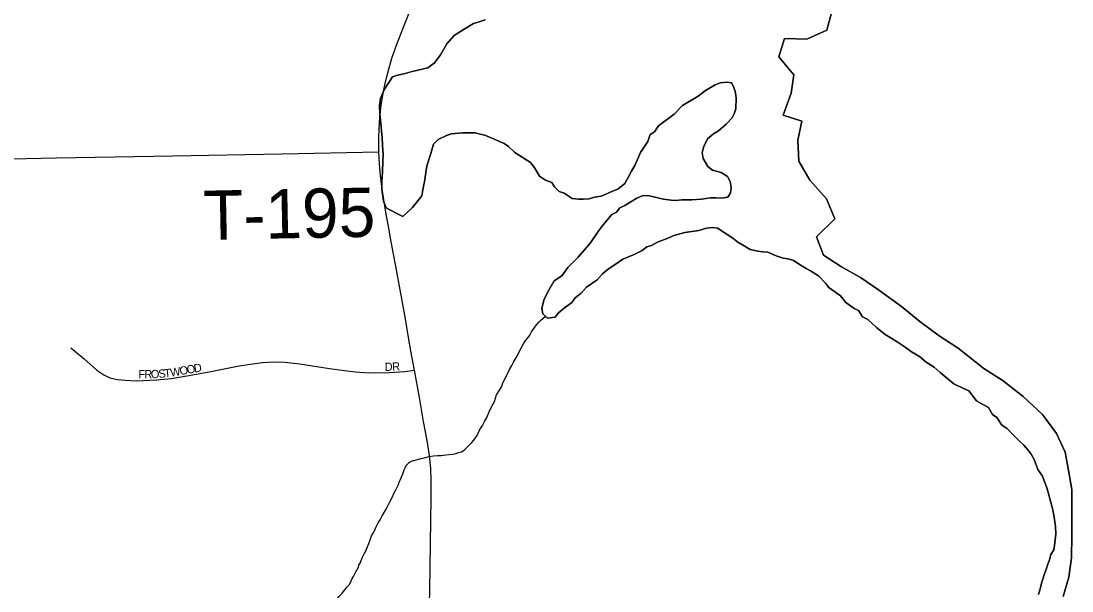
# Model space of a CAD drawing. Extents: x -10.1 to 68, y -9.5 to 29.2.
# Drawn here: x 4.36 to 5.573, y 17.444 to 18.102 of the extents above; entities that cross this region are included whole.
import ezdxf

# ---------------------------------------------------------------- set-up
doc = ezdxf.new("R2010")
doc.units = 0
for name, color, linetype in [('GM_X_Major_Lake', 7, 'Continuous'), ('GM_X_Major_River', 7, 'Continuous'), ('GM_X_Minor_River', 7, 'Continuous'), ('GM_X_Township_Road', 7, 'Continuous'), ('GM_X_Township_Road_Text', 7, 'Continuous'), ('GM_X_Township_Subdivision', 7, 'Continuous'), ('GM_X_Township_Subdivision_Text', 7, 'Continuous'), ('SH_Data', 7, 'Continuous')]:
    doc.layers.add(name, color=color, linetype=linetype)

msp = doc.modelspace()

# ---------------------------------------------------------------- linework, layer by layer
at = {"layer": 'GM_X_Major_Lake'}
for points in [[(4.896, 18.1037), (4.8877, 18.1009), (4.8824, 18.0993), (4.8715, 18.0927), (4.8602, 18.0854), (4.8516, 18.0758), (4.8442, 18.0631), (4.8375, 18.0539), (4.8296, 18.0481), (4.8115, 18.0441), (4.8035, 18.0417), (4.7937, 18.0393), (4.7888, 18.0377), (4.7799, 18.0235), (4.7751, 18.0132), (4.774, 18.0048), (4.7745, 17.995), (4.7754, 17.9843), (4.7763, 17.9752), (4.7771, 17.9676), (4.7776, 17.9589), (4.7781, 17.9479), (4.7778, 17.9403), (4.7776, 17.9277), (4.7766, 17.9171), (4.7767, 17.9087), (4.7784, 17.8943), (4.7815, 17.8867), (4.7933, 17.8804), (4.8009, 17.8767), (4.8122, 17.8871), (4.8226, 17.9006), (4.824, 17.9074), (4.8262, 17.9189), (4.8276, 17.9303), (4.829, 17.9364), (4.833, 17.9494), (4.8363, 17.96), (4.8415, 17.9654), (4.8513, 17.9701), (4.857, 17.9721), (4.8699, 17.973), (4.8843, 17.9732), (4.89, 17.9717), (4.8953, 17.9703), (4.9063, 17.9659), (4.9178, 17.9607), (4.9227, 17.9573), (4.93, 17.9506), (4.9483, 17.939), (4.9533, 17.9323), (4.9587, 17.9232), (4.9656, 17.9187), (4.9728, 17.9158), (4.9759, 17.9109), (4.9813, 17.9056), (4.987, 17.9034), (4.9962, 17.8975), (5.0038, 17.8964), (5.0091, 17.8965)], [(5.286, 17.832), (5.2782, 17.8532), (5.2991, 17.874), (5.2898, 17.897), (5.2706, 17.9184), (5.2578, 17.9403), (5.2564, 17.9646), (5.2611, 17.9867), (5.2398, 17.9937), (5.2489, 18.0189), (5.2521, 18.0402), (5.2348, 18.0609), (5.241, 18.0822), (5.2671, 18.0814), (5.2901, 18.0916), (5.2959, 18.1133)], [(5.0091, 17.8965), (5.0159, 17.897), (5.0219, 17.8989), (5.0295, 17.9002), (5.0344, 17.9018), (5.0427, 17.9057), (5.0491, 17.908), (5.057, 17.9146), (5.0614, 17.9222), (5.0647, 17.9291), (5.0688, 17.9364), (5.0751, 17.9505), (5.0837, 17.9632), (5.0862, 17.9712), (5.0911, 17.9743), (5.096, 17.9812), (5.114, 17.9947), (5.1237, 18.0047), (5.1331, 18.0106), (5.1414, 18.0156), (5.15, 18.0222), (5.1613, 18.0284), (5.167, 18.0307), (5.1749, 18.0316), (5.1802, 18.0309), (5.1829, 18.026), (5.1845, 18.0192), (5.1854, 18.0131), (5.1851, 18.001), (5.1833, 17.9952), (5.1807, 17.9903), (5.174, 17.9833), (5.165, 17.9756), (5.1593, 17.9721), (5.1522, 17.9663), (5.1481, 17.9575), (5.1463, 17.9503), (5.1472, 17.9435), (5.1529, 17.9344), (5.1583, 17.9299), (5.1682, 17.9274), (5.1754, 17.9229), (5.1785, 17.9169), (5.1798, 17.9101), (5.1787, 17.904), (5.1757, 17.899), (5.1678, 17.8977), (5.1617, 17.8981), (5.1557, 17.898), (5.1507, 17.8972), (5.1454, 17.8967), (5.1341, 17.8958), (5.1227, 17.8957), (5.1155, 17.8952), (5.1106, 17.8955), (5.1015, 17.8965), (5.0966, 17.8976), (5.0855, 17.9005), (5.078, 17.9008), (5.0708, 17.8977), (5.0569, 17.8891), (5.0512, 17.8864), (5.0475, 17.8814), (5.0418, 17.879), (5.0321, 17.8671), (5.0262, 17.8591), (5.0172, 17.846), (5.0127, 17.8407), (5.003, 17.8295), (4.9914, 17.8176), (4.9843, 17.808), (4.9753, 17.8022), (4.9683, 17.7896), (4.9635, 17.78), (4.9613, 17.7705), (4.9625, 17.7644), (4.9679, 17.7592), (4.9766, 17.7604), (4.9803, 17.7654), (4.987, 17.7708), (4.9957, 17.7774), (4.9998, 17.7827), (5.0065, 17.7881), (5.0129, 17.7951), (5.0249, 17.8036), (5.0313, 17.8105), (5.038, 17.8163), (5.0482, 17.8229), (5.0546, 17.8275), (5.0678, 17.8326), (5.0768, 17.8373), (5.0824, 17.8416), (5.0877, 17.8431), (5.0945, 17.847), (5.1077, 17.8518), (5.1134, 17.8545), (5.1262, 17.8581), (5.1368, 17.8597), (5.1425, 17.8606), (5.1511, 17.8633), (5.1583, 17.8638)], [(5.1583, 17.8638), (5.164, 17.8631), (5.1717, 17.8583), (5.1816, 17.8516), (5.1873, 17.8471), (5.1946, 17.8426), (5.2014, 17.8385), (5.2105, 17.8367), (5.2162, 17.8357), (5.2219, 17.8354), (5.2314, 17.8313), (5.2398, 17.8284), (5.2455, 17.8277), (5.2516, 17.8259), (5.2604, 17.8199), (5.2661, 17.8165), (5.2711, 17.8139), (5.2806, 17.808)], [(5.5626, 17.438), (5.5692, 17.4601), (5.5723, 17.4826), (5.5728, 17.5081), (5.5728, 17.5366), (5.5726, 17.5613), (5.5689, 17.5833), (5.5649, 17.6045), (5.5551, 17.626), (5.539, 17.6482), (5.5164, 17.6689), (5.4934, 17.6868), (5.4713, 17.701), (5.4414, 17.7245), (5.4197, 17.7387), (5.3975, 17.7555), (5.3761, 17.7727), (5.3497, 17.7918), (5.3287, 17.8063), (5.307, 17.8186), (5.286, 17.832)], [(5.2806, 17.808), (5.2883, 17.7997), (5.2925, 17.7945), (5.3059, 17.7851), (5.312, 17.7772), (5.3216, 17.7705), (5.3265, 17.7679), (5.3312, 17.7607), (5.3373, 17.7578), (5.3472, 17.7484), (5.3575, 17.7402), (5.3652, 17.7357), (5.3713, 17.732), (5.3804, 17.7256), (5.3877, 17.7204), (5.3969, 17.7148), (5.4045, 17.7085), (5.4137, 17.7025), (5.4209, 17.6965), (5.4278, 17.6909), (5.4366, 17.6834), (5.4477, 17.6779), (5.4538, 17.6753), (5.4626, 17.664), (5.4714, 17.6588), (5.4767, 17.6562), (5.481, 17.6479), (5.4863, 17.6445), (5.4921, 17.6359), (5.4982, 17.6318), (5.5025, 17.6269), (5.5117, 17.6179), (5.5174, 17.6126), (5.522, 17.6074), (5.5259, 17.6021), (5.5293, 17.5961), (5.5333, 17.5847), (5.5387, 17.5768), (5.5414, 17.5696), (5.5433, 17.5647), (5.5449, 17.5594), (5.5481, 17.548), (5.5505, 17.5397), (5.5521, 17.5317), (5.5537, 17.5192), (5.5542, 17.5101), (5.5525, 17.4968), (5.5518, 17.4918), (5.5484, 17.4865), (5.547, 17.4804), (5.5448, 17.4754), (5.543, 17.4693), (5.5411, 17.4643), (5.5378, 17.4533), (5.5364, 17.4479), (5.5342, 17.4403)]]:
    msp.add_lwpolyline(points, dxfattribs=at)
at = {"layer": 'GM_X_Major_River'}
for points in [[(5.0091, 17.8965), (5.0038, 17.8964), (4.9962, 17.8975), (4.987, 17.9034), (4.9813, 17.9056), (4.9759, 17.9109), (4.9728, 17.9158), (4.9656, 17.9187), (4.9587, 17.9232), (4.9533, 17.9323), (4.9483, 17.939), (4.93, 17.9506), (4.9227, 17.9573), (4.9178, 17.9607), (4.9063, 17.9659), (4.8953, 17.9703), (4.89, 17.9717), (4.8843, 17.9732), (4.8699, 17.973), (4.857, 17.9721), (4.8513, 17.9701), (4.8415, 17.9654), (4.8363, 17.96), (4.833, 17.9494), (4.829, 17.9364), (4.8276, 17.9303), (4.8262, 17.9189), (4.824, 17.9074), (4.8226, 17.9006), (4.8122, 17.8871), (4.8009, 17.8767), (4.7933, 17.8804), (4.7815, 17.8867), (4.7784, 17.8943), (4.7767, 17.9087), (4.7766, 17.9171), (4.7776, 17.9277), (4.7778, 17.9403), (4.7781, 17.9479), (4.7776, 17.9589), (4.7771, 17.9676), (4.7763, 17.9752), (4.7754, 17.9843), (4.7745, 17.995), (4.774, 18.0048), (4.7751, 18.0132), (4.7799, 18.0235), (4.7888, 18.0377), (4.7937, 18.0393), (4.8035, 18.0417), (4.8115, 18.0441), (4.8296, 18.0481), (4.8375, 18.0539), (4.8442, 18.0631), (4.8516, 18.0758), (4.8602, 18.0854), (4.8715, 18.0927), (4.8824, 18.0993), (4.8877, 18.1009), (4.896, 18.1037)], [(5.2959, 18.1133), (5.2901, 18.0916), (5.2671, 18.0814), (5.241, 18.0822), (5.2348, 18.0609), (5.2521, 18.0402), (5.2489, 18.0189), (5.2398, 17.9937), (5.2611, 17.9867), (5.2564, 17.9646), (5.2578, 17.9403), (5.2706, 17.9184), (5.2898, 17.897), (5.2991, 17.874), (5.2782, 17.8532), (5.286, 17.832)], [(5.1583, 17.8638), (5.1511, 17.8633), (5.1425, 17.8606), (5.1368, 17.8597), (5.1262, 17.8581), (5.1134, 17.8545), (5.1077, 17.8518), (5.0945, 17.847), (5.0877, 17.8431), (5.0824, 17.8416), (5.0768, 17.8373), (5.0678, 17.8326), (5.0546, 17.8275), (5.0482, 17.8229), (5.038, 17.8163), (5.0313, 17.8105), (5.0249, 17.8036), (5.0129, 17.7951), (5.0065, 17.7881), (4.9998, 17.7827), (4.9957, 17.7774), (4.987, 17.7708), (4.9803, 17.7654), (4.9766, 17.7604), (4.9679, 17.7592), (4.9625, 17.7644), (4.9613, 17.7705), (4.9635, 17.78), (4.9683, 17.7896), (4.9753, 17.8022), (4.9843, 17.808), (4.9914, 17.8176), (5.003, 17.8295), (5.0127, 17.8407), (5.0172, 17.846), (5.0262, 17.8591), (5.0321, 17.8671), (5.0418, 17.879), (5.0475, 17.8814), (5.0512, 17.8864), (5.0569, 17.8891), (5.0708, 17.8977), (5.078, 17.9008), (5.0855, 17.9005), (5.0966, 17.8976), (5.1015, 17.8965), (5.1106, 17.8955), (5.1155, 17.8952), (5.1227, 17.8957), (5.1341, 17.8958), (5.1454, 17.8967), (5.1507, 17.8972), (5.1557, 17.898), (5.1617, 17.8981), (5.1678, 17.8977), (5.1757, 17.899), (5.1787, 17.904), (5.1798, 17.9101), (5.1785, 17.9169), (5.1754, 17.9229), (5.1682, 17.9274), (5.1583, 17.9299), (5.1529, 17.9344), (5.1472, 17.9435), (5.1463, 17.9503), (5.1481, 17.9575), (5.1522, 17.9663), (5.1593, 17.9721), (5.165, 17.9756), (5.174, 17.9833), (5.1807, 17.9903), (5.1833, 17.9952), (5.1851, 18.001), (5.1854, 18.0131), (5.1845, 18.0192), (5.1829, 18.026), (5.1802, 18.0309), (5.1749, 18.0316), (5.167, 18.0307), (5.1613, 18.0284), (5.15, 18.0222), (5.1414, 18.0156), (5.1331, 18.0106), (5.1237, 18.0047), (5.114, 17.9947), (5.096, 17.9812), (5.0911, 17.9743), (5.0862, 17.9712), (5.0837, 17.9632), (5.0751, 17.9505), (5.0688, 17.9364), (5.0647, 17.9291), (5.0614, 17.9222), (5.057, 17.9146), (5.0491, 17.908), (5.0427, 17.9057), (5.0344, 17.9018), (5.0295, 17.9002), (5.0219, 17.8989), (5.0159, 17.897), (5.0091, 17.8965)], [(5.2806, 17.808), (5.2711, 17.8139), (5.2661, 17.8165), (5.2604, 17.8199), (5.2516, 17.8259), (5.2455, 17.8277), (5.2398, 17.8284), (5.2314, 17.8313), (5.2219, 17.8354), (5.2162, 17.8357), (5.2105, 17.8367), (5.2014, 17.8385), (5.1946, 17.8426), (5.1873, 17.8471), (5.1816, 17.8516), (5.1717, 17.8583), (5.164, 17.8631), (5.1583, 17.8638)], [(5.286, 17.832), (5.307, 17.8186), (5.3287, 17.8063), (5.3497, 17.7918), (5.3761, 17.7727), (5.3975, 17.7555), (5.4197, 17.7387), (5.4414, 17.7245), (5.4713, 17.701), (5.4934, 17.6868), (5.5164, 17.6689), (5.539, 17.6482), (5.5551, 17.626), (5.5649, 17.6045), (5.5689, 17.5833), (5.5726, 17.5613), (5.5728, 17.5366), (5.5728, 17.5081), (5.5723, 17.4826), (5.5692, 17.4601), (5.5626, 17.438)], [(5.5342, 17.4403), (5.5364, 17.4479), (5.5378, 17.4533), (5.5411, 17.4643), (5.543, 17.4693), (5.5448, 17.4754), (5.547, 17.4804), (5.5484, 17.4865), (5.5518, 17.4918), (5.5525, 17.4968), (5.5542, 17.5101), (5.5537, 17.5192), (5.5521, 17.5317), (5.5505, 17.5397), (5.5481, 17.548), (5.5449, 17.5594), (5.5433, 17.5647), (5.5414, 17.5696), (5.5387, 17.5768), (5.5333, 17.5847), (5.5293, 17.5961), (5.5259, 17.6021), (5.522, 17.6074), (5.5174, 17.6126), (5.5117, 17.6179), (5.5025, 17.6269), (5.4982, 17.6318), (5.4921, 17.6359), (5.4863, 17.6445), (5.481, 17.6479), (5.4767, 17.6562), (5.4714, 17.6588), (5.4626, 17.664), (5.4538, 17.6753), (5.4477, 17.6779), (5.4366, 17.6834), (5.4278, 17.6909), (5.4209, 17.6965), (5.4137, 17.7025), (5.4045, 17.7085), (5.3969, 17.7148), (5.3877, 17.7204), (5.3804, 17.7256), (5.3713, 17.732), (5.3652, 17.7357), (5.3575, 17.7402), (5.3472, 17.7484), (5.3373, 17.7578), (5.3312, 17.7607), (5.3265, 17.7679), (5.3216, 17.7705), (5.312, 17.7772), (5.3059, 17.7851), (5.2925, 17.7945), (5.2883, 17.7997), (5.2806, 17.808)]]:
    msp.add_lwpolyline(points, dxfattribs=at)
at = {"layer": 'GM_X_Minor_River'}
for points in [[(4.7419, 17.4578), (4.7441, 17.4609), (4.7452, 17.4632), (4.7466, 17.4663), (4.7481, 17.4693), (4.7496, 17.472), (4.7503, 17.4743), (4.7517, 17.4766), (4.7528, 17.4797), (4.7542, 17.4832), (4.7561, 17.4874), (4.7583, 17.4905), (4.7597, 17.4947), (4.7615, 17.4993), (4.7633, 17.5035), (4.7647, 17.5078), (4.7665, 17.5112), (4.7684, 17.5147), (4.7702, 17.5185), (4.7724, 17.5228), (4.7746, 17.5266), (4.7771, 17.5309), (4.7804, 17.5367), (4.783, 17.5417), (4.7859, 17.5471), (4.7884, 17.5521), (4.7906, 17.5567), (4.7924, 17.5605), (4.7943, 17.564), (4.7957, 17.5674), (4.7968, 17.5698), (4.7979, 17.5721), (4.8008, 17.5794), (4.8015, 17.5817), (4.8025, 17.5843), (4.8036, 17.5866), (4.8047, 17.589), (4.8081, 17.5928), (4.8107, 17.594), (4.8133, 17.5949), (4.8164, 17.5957), (4.8205, 17.5969), (4.8254, 17.5982), (4.8311, 17.5995), (4.8364, 17.6003), (4.841, 17.6008), (4.8452, 17.6009), (4.8505, 17.6014), (4.8543, 17.6019), (4.8581, 17.6023), (4.8622, 17.6032), (4.8656, 17.604), (4.8687, 17.6049), (4.8705, 17.6061), (4.8724, 17.6076), (4.875, 17.6103), (4.8776, 17.6131), (4.8802, 17.6154), (4.8828, 17.6185), (4.8846, 17.6212), (4.8865, 17.6239), (4.8879, 17.6266), (4.8898, 17.6308), (4.8927, 17.6355), (4.8949, 17.6401), (4.8978, 17.6447), (4.9003, 17.6513), (4.9036, 17.6578), (4.9065, 17.6632), (4.909, 17.6709), (4.9123, 17.6763), (4.9149, 17.6805), (4.9163, 17.6847), (4.9185, 17.689), (4.9239, 17.7001), (4.9265, 17.7047), (4.9287, 17.7086), (4.9309, 17.7124), (4.9331, 17.7163), (4.936, 17.7221), (4.9382, 17.7263), (4.9404, 17.7302), (4.9429, 17.734), (4.9455, 17.7371), (4.9474, 17.7398), (4.9492, 17.7433), (4.9514, 17.746), (4.9533, 17.7487), (4.9551, 17.7514), (4.9577, 17.7545), (4.9596, 17.7565), (4.9653, 17.7617)], [(4.7097, 17.4194), (4.7168, 17.4218), (4.7219, 17.4318), (4.7275, 17.438), (4.7308, 17.4419), (4.7338, 17.4458), (4.7368, 17.4493), (4.739, 17.4516), (4.7404, 17.4543), (4.7419, 17.4578)]]:
    msp.add_lwpolyline(points, dxfattribs=at)
at = {"layer": 'GM_X_Township_Road'}
msp.add_lwpolyline([(4.7732, 17.9507), (4.6614, 17.9487), (4.5354, 17.9464), (4.4015, 17.9439), (4.0507, 17.9362), (3.9932, 17.9347), (3.9463, 17.934), (3.8941, 17.9335), (3.8306, 17.932), (3.7646, 17.9303), (3.6584, 17.9291)], dxfattribs=at)
at = {"layer": 'GM_X_Township_Subdivision'}
msp.add_lwpolyline([(4.4177, 17.7251), (4.4333, 17.7124), (4.4478, 17.6994), (4.456, 17.6937), (4.463, 17.6905), (4.4712, 17.6885), (4.4804, 17.6875), (4.4931, 17.687), (4.517, 17.6882), (4.5339, 17.6897), (4.5539, 17.6932), (4.5792, 17.6977), (4.6121, 17.7042), (4.6278, 17.7067), (4.639, 17.7081), (4.6527, 17.7089), (4.6646, 17.7084), (4.6821, 17.7067), (4.7162, 17.7012), (4.7334, 17.6987), (4.7461, 17.6974), (4.7618, 17.6962), (4.7854, 17.6967), (4.8031, 17.6977), (4.8145, 17.6992)], dxfattribs=at)
at = {"layer": 'SH_Data'}
for points in [[(4.7864, 17.8536), (4.7854, 17.859), (4.7817, 17.8794), (4.7769, 17.9081), (4.7752, 17.9238), (4.774, 17.9372), (4.7732, 17.9507), (4.773, 17.9664), (4.7734, 17.9782), (4.7742, 17.9907), (4.7757, 18.0051), (4.7785, 18.0207), (4.7812, 18.0336), (4.7852, 18.0483), (4.7886, 18.0605), (4.7936, 18.0744), (4.8015, 18.095), (4.8105, 18.1174)], [(4.8309, 17.3996), (4.8319, 17.4455), (4.8337, 17.5519), (4.8337, 17.5718), (4.8333, 17.5858), (4.8315, 17.6009), (4.8288, 17.618), (4.8247, 17.6401), (4.82, 17.6678), (4.8145, 17.6992), (4.8105, 17.7194), (4.8071, 17.7394), (4.8038, 17.7584), (4.7936, 17.8152), (4.7864, 17.8536)]]:
    msp.add_lwpolyline(points, dxfattribs=at)

# ---------------------------------------------------------------- texts
at = {"layer": 'GM_X_Township_Road_Text'}
msp.add_text('T-195', height=0.05682, rotation=1.1227, dxfattribs=at).set_placement((4.5711, 17.8495))
at = {"layer": 'GM_X_Township_Subdivision_Text'}
for s, rotation, p in [('W', 9.4143, (4.5333, 17.6916)), ('O', 10.3038, (4.5442, 17.6934)), ('O', 10.3068, (4.5524, 17.6949)), ('D', 10.2853, (4.5606, 17.6964)), ('D', 1.8363, (4.7801, 17.6983)), ('R', 3.6098, (4.7888, 17.6985)), ('F', 0.082, (4.4959, 17.6899)), ('R', 0.0729, (4.5026, 17.6899)), ('O', 1.6603, (4.5103, 17.6899)), ('S', 5.0571, (4.5193, 17.6902)), ('T', 6.1461, (4.5261, 17.6908))]:
    msp.add_text(s, height=0.00947, rotation=rotation, dxfattribs=at).set_placement(p)

doc.saveas('drawing.dxf')
